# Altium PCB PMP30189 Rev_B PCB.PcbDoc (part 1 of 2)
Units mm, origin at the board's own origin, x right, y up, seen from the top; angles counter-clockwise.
Board outline 62.23 x 71.12 mm, 4 copper layers (Top Layer, Signal Layer 1, Signal Layer 2, Bottom Layer), stack 2.099 mm thick; 88 components, 42 nets, 247 pads, 90 vias.
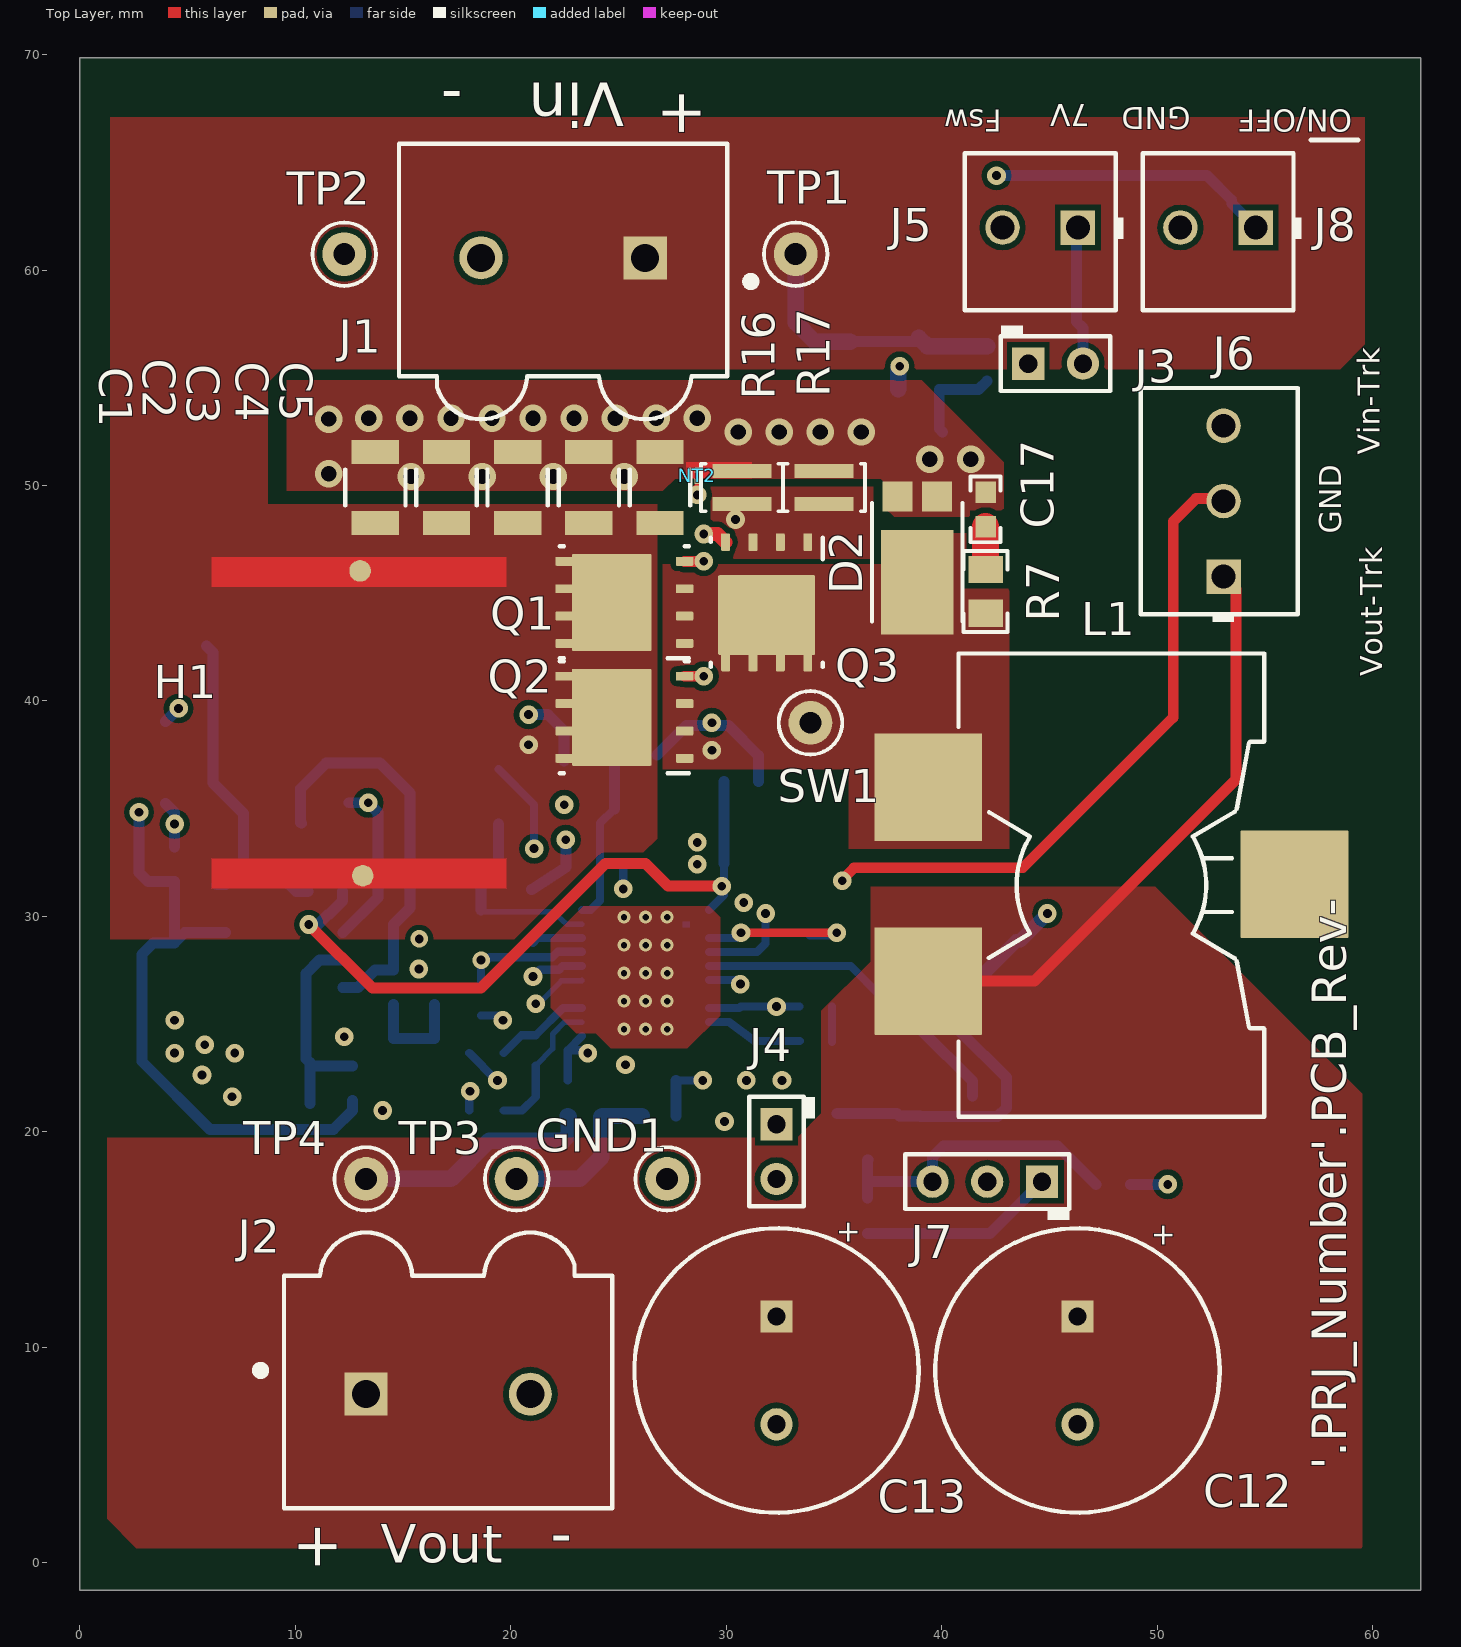
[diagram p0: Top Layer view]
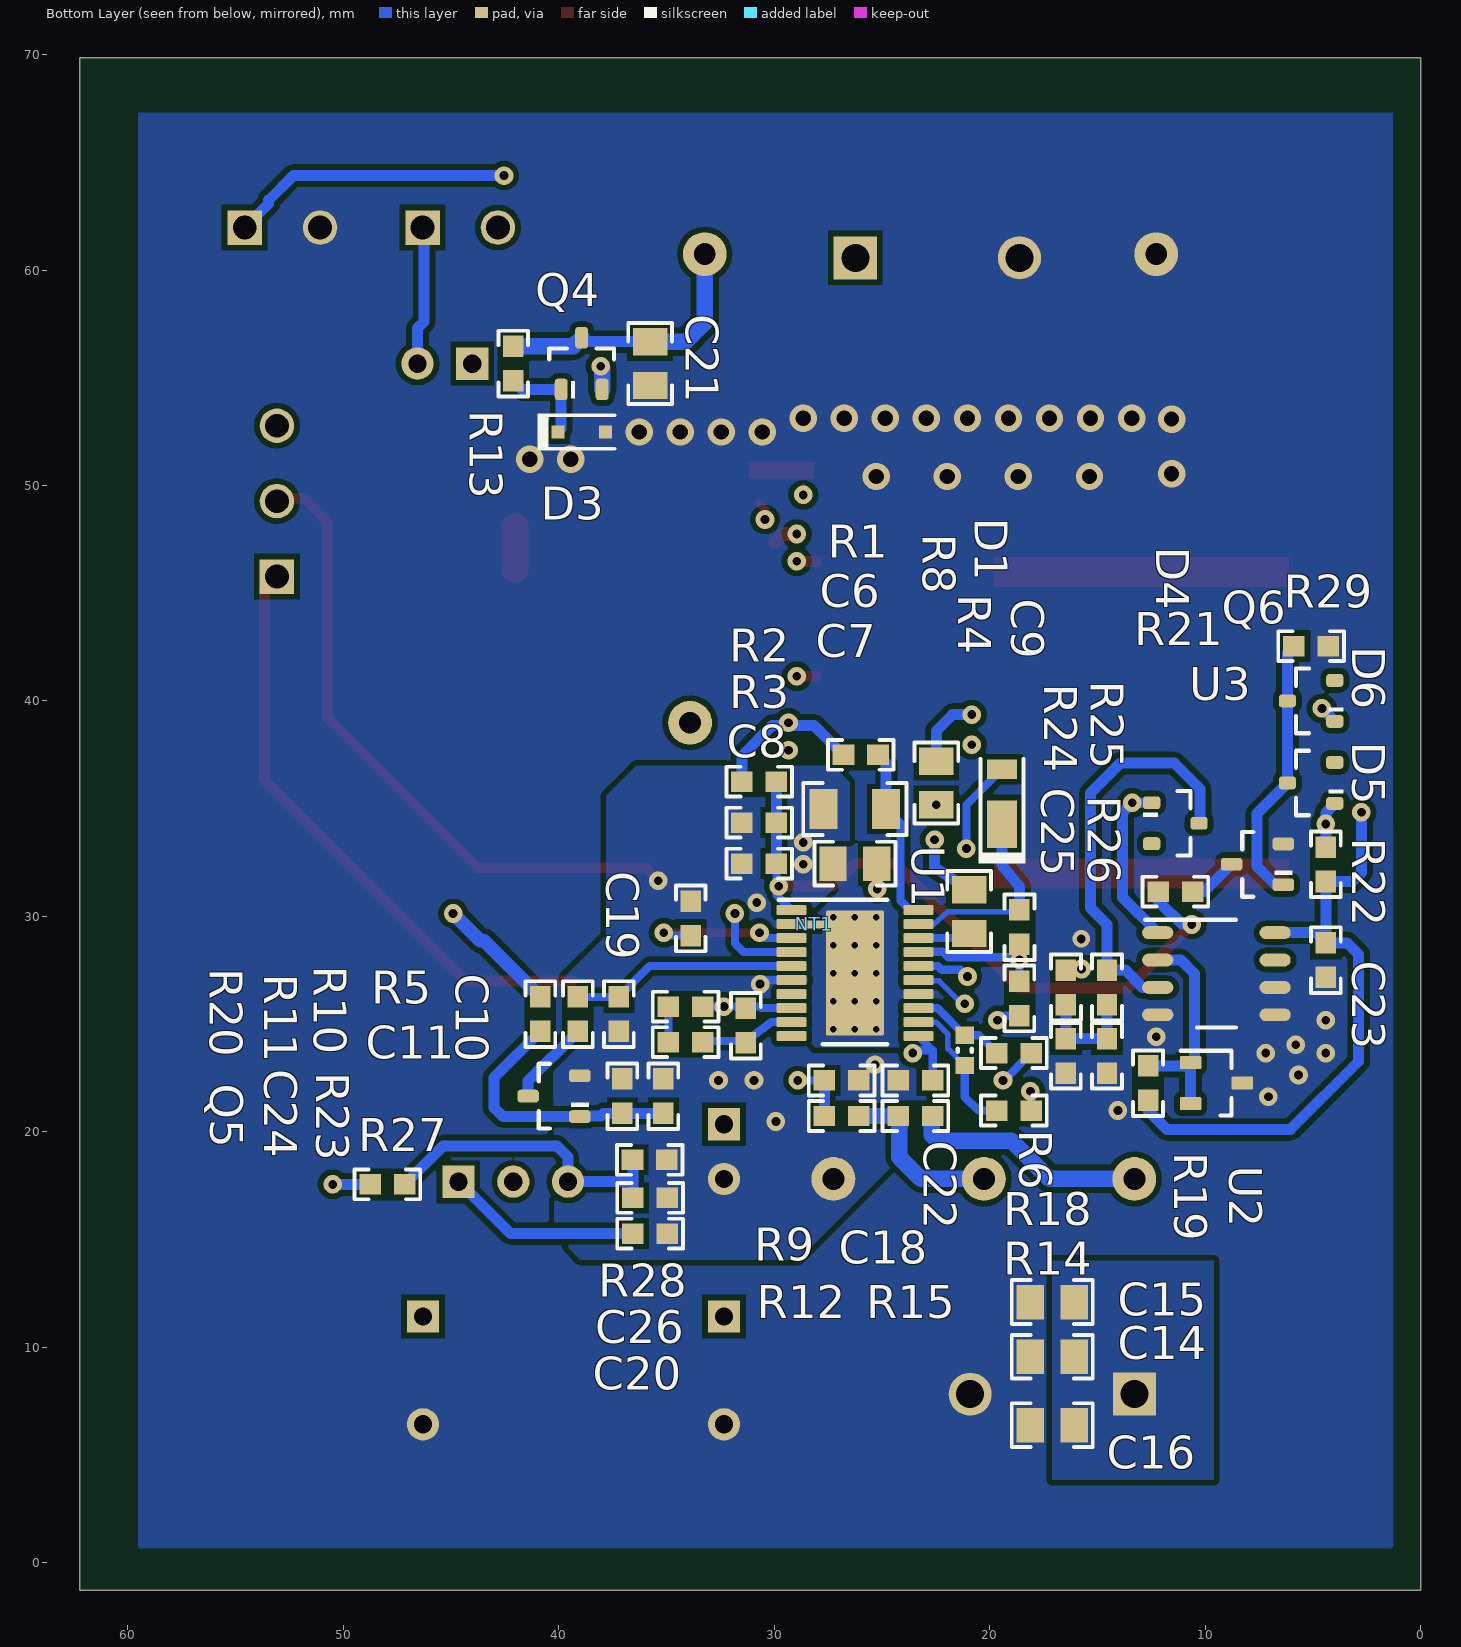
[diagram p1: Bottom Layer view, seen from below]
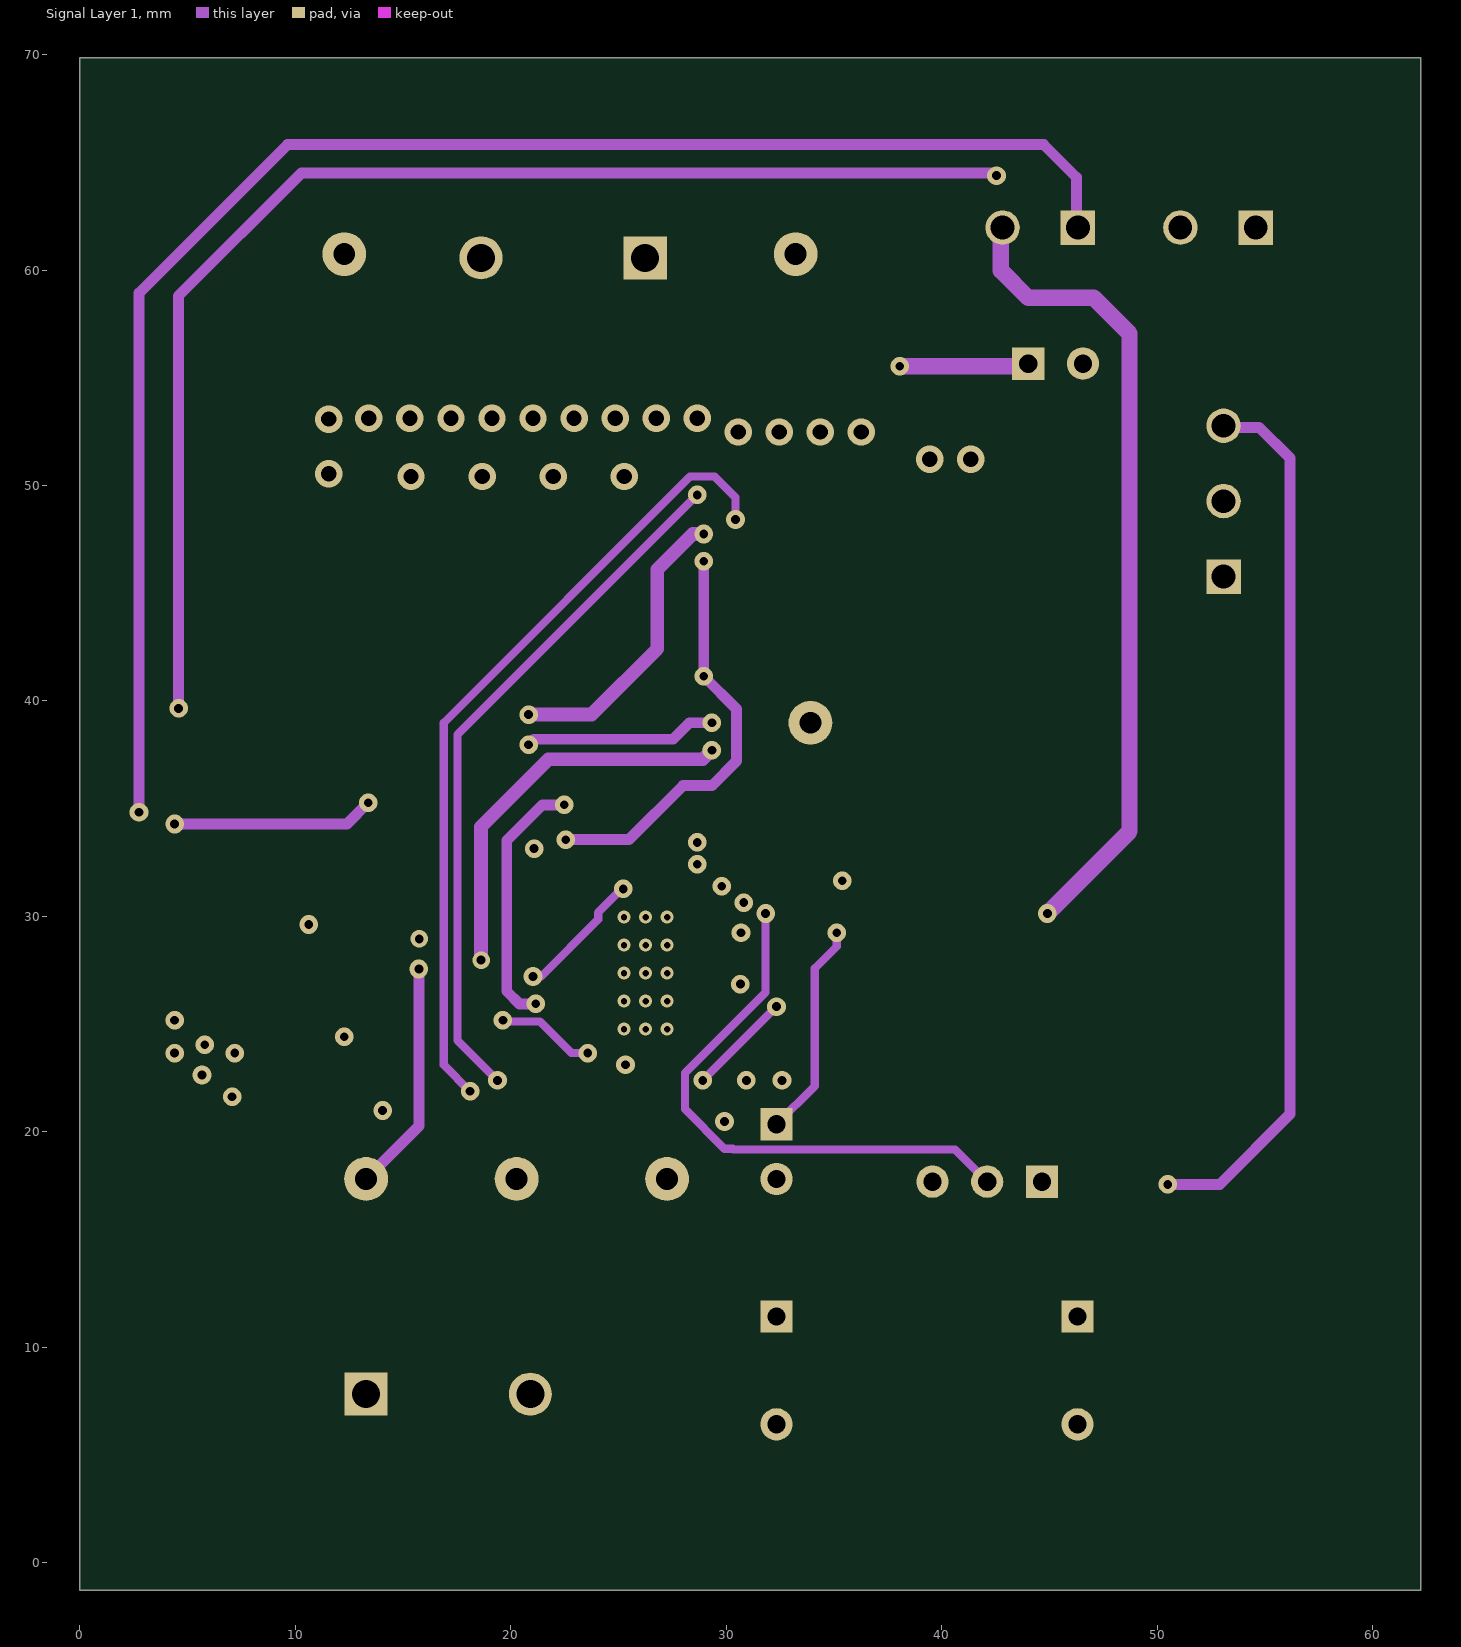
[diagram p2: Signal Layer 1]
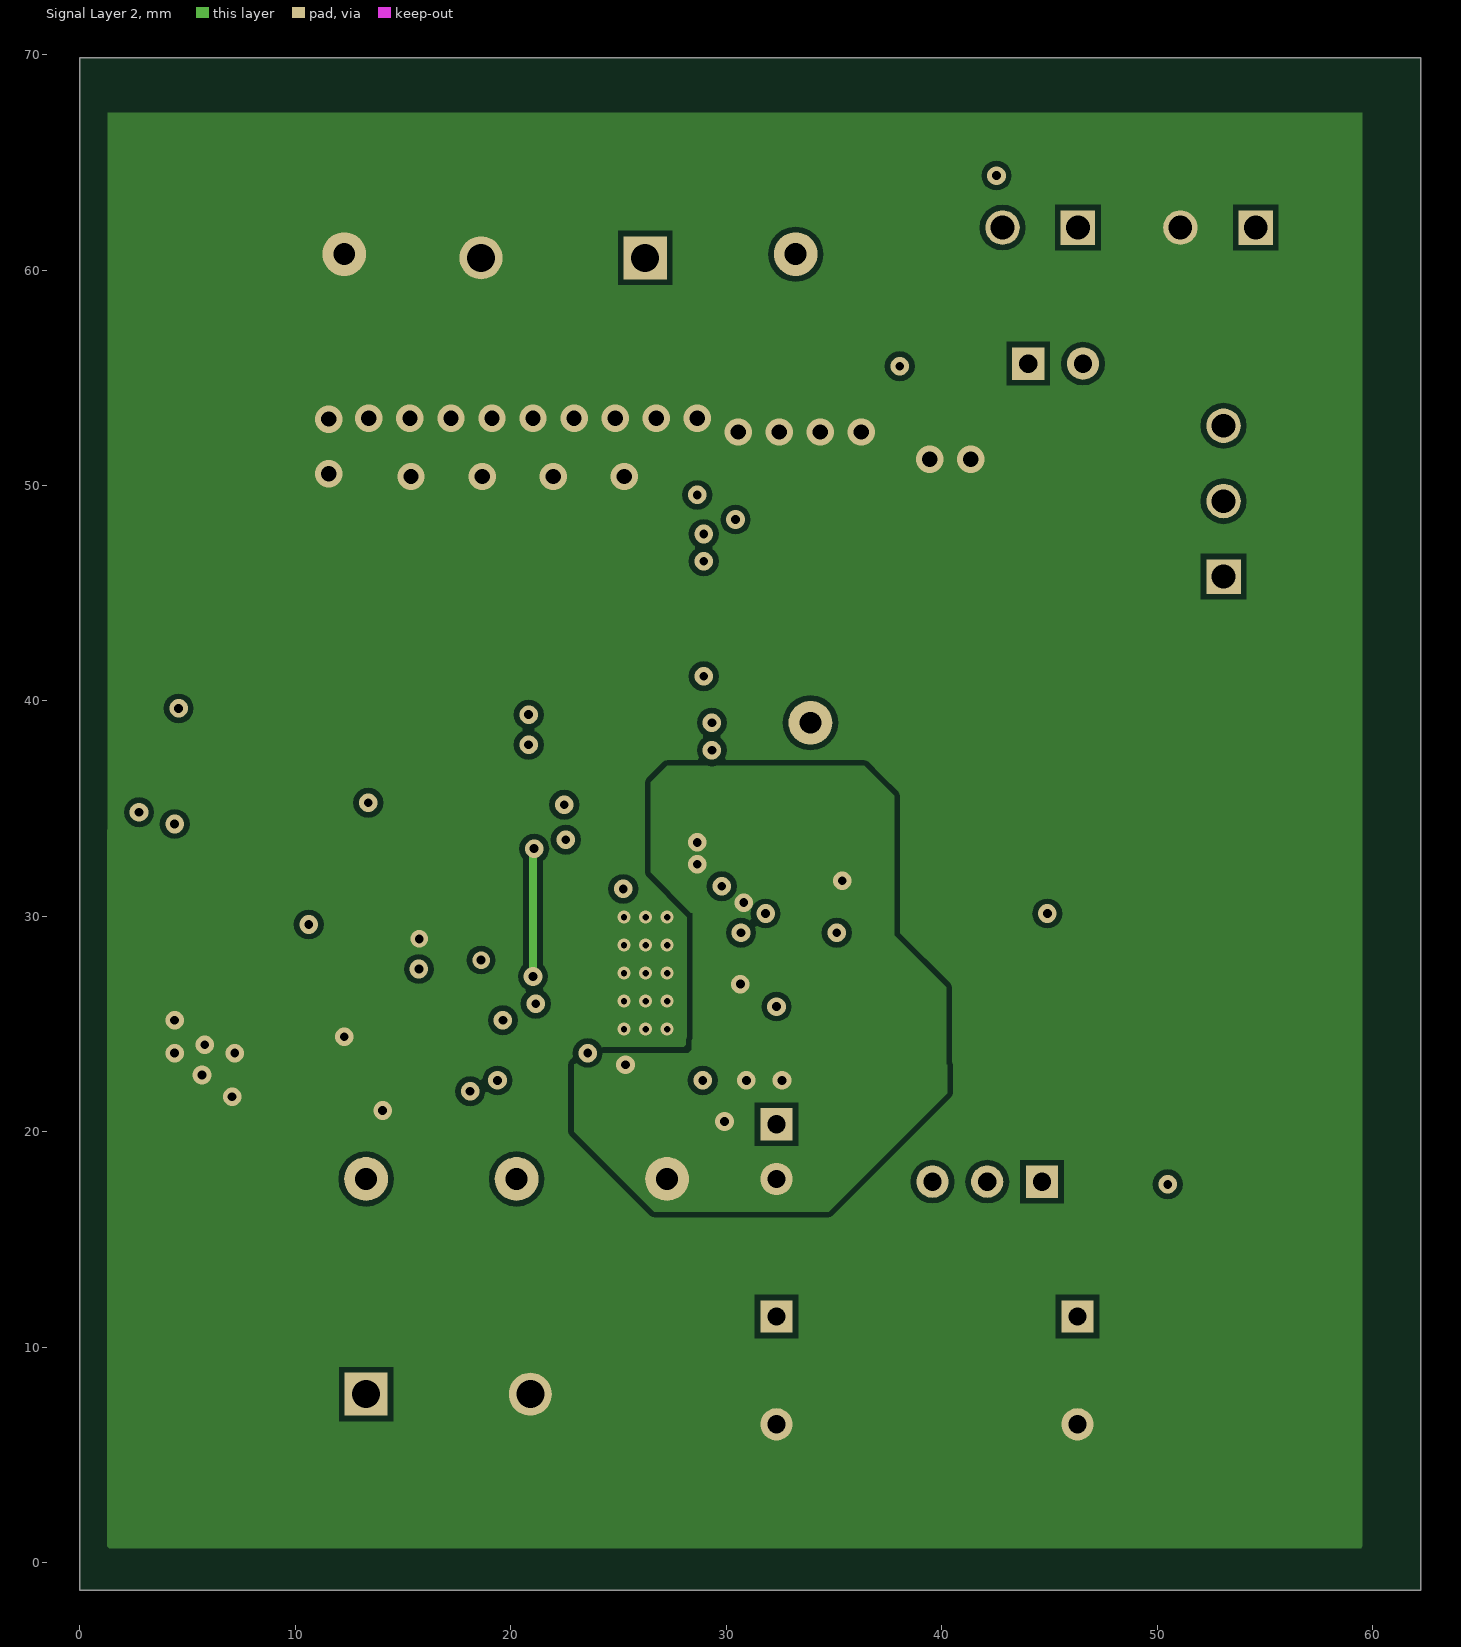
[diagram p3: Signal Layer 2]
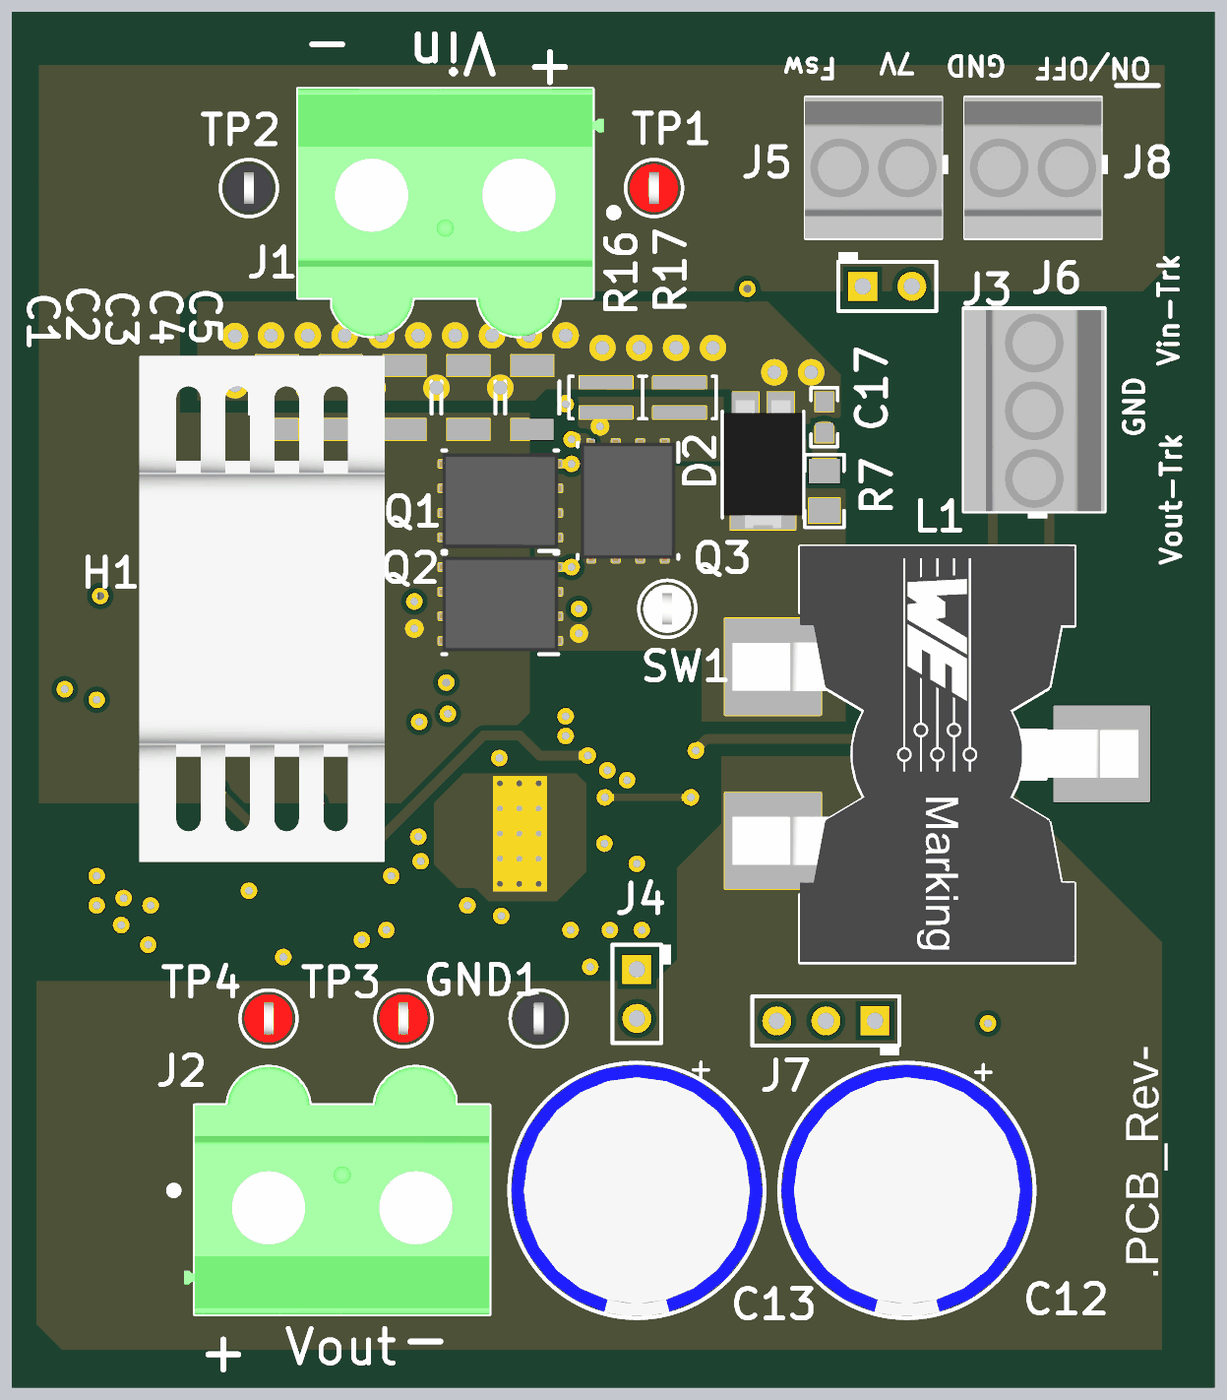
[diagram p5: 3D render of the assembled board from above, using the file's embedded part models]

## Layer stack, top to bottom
Top Solder: solder mask 0.0102, Solder Resist, Dk 3.5
Top Layer: signal copper 0.0711
Dielectric1: core 1.5037, FR-4, Dk 4.8
Signal Layer 1: signal copper 0.036
Dielectric 3: prepreg 0.127, Dk 4.2
Signal Layer 2: signal copper 0.036
Dielectric 2: core 0.254, Dk 4.2
Bottom Layer: signal copper 0.0711
Bottom Solder: solder mask 0.0102, Solder Resist, Dk 3.5

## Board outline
0,-1.27 62.23,-1.27 62.23,69.85 0,69.85

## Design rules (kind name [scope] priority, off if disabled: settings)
AcuteAngle [All] p1: minimum=4.50000000000000E+0001 checktracksonly=FALSE
AssemblyTestPointUsage [All] p1: valid=2
BoardOutlineClearance BoardOutlineClearance_MountingHoles [OnCopper and InComponentClass('Mounting Holes')] p1: gap=1.016
BoardOutlineClearance BoardOutlineClearance_Poly [OnCopper and IsPoly] p2: gap=0.635
BoardOutlineClearance [OnCopper and Not InComponentClass('Logo') and not InComponentClass('FiducialMark') and not InRegion(1000,500,4000,800) and not InPoly] p3: gap=1.905
Clearance Clearance_Keepouts [((IsTrack Or IsArc) And Not InPoly) And IsFree and IsKeepOut vs ((IsTrack Or IsArc) And Not InPoly) And IsFree and IsKeepOut] p1: gap=0
Clearance Clearance_Poly [InPolygon] p2: gap=0.254
Clearance [All] p3: gap=0.2
ComponentClearance ComponentClearance_MountingHoles_FiducialMarks [InComponentClass('Mounting Holes') vs InComponentClass('FiducialMark')] p1: gap=1.27 collisioncheckmode=3 verticalgap=0.254 showdistances=FALSE
ComponentClearance ComponentClearance_Shunt [InComponentClass('Header') vs InComponentClass('Shunt')] p2: gap=0 collisioncheckmode=3 verticalgap=0 showdistances=FALSE
ComponentClearance ComponentClearance_Logo [InComponentClass('Logo')] p3: gap=1.27 collisioncheckmode=3 verticalgap=0.254 showdistances=FALSE
ComponentClearance ComponentClearance_ScrewToNut [(HasFootprint('NY PMS 440 0025 PH')) vs (HasFootprint('Keystone_1902C'))] p4: gap=0.127 collisioncheckmode=3 verticalgap=0.254 showdistances=FALSE
ComponentClearance ComponentClearance_MountingHoles [InComponentClass('Mounting Holes')] p5: gap=6.35 collisioncheckmode=3 verticalgap=2540 showdistances=FALSE
ComponentClearance ComponentClearance_SmallPassives [HasFootprint('0201*') or HasFootprint('0402*') or HasFootprint('0508') or HasFootprint('0603*') or HasFootprint('0612') or HasFootprint('0805*') or HasFootprint('0815*') or HasFootprint('0830*') or HasFootprint('1206*') or HasFootprint('1210*') or HasFootprint('1808*') or HasFootprint('1812*') or HasFootprint('1825*') or HasFootprint('2010*') or HasFootprint('2220*') or HasFootprint('2225*') or HasFootprint('2512*') or HasFootprint('2728*') or HasFootprint('3518*') vs HasFootprint('0201*') or HasFootprint('0402*') or HasFootprint('0508') or HasFootprint('0603*') or HasFootprint('0612') or HasFootprint('0805*') or HasFootprint('0815*') or HasFootprint('0830*') or HasFootprint('1206*') or HasFootprint('1210*') or HasFootprint('1808*') or HasFootprint('1812*') or HasFootprint('1825*') or HasFootprint('2010*') or HasFootprint('2220*') or HasFootprint('2225*') or HasFootprint('2512*') or HasFootprint('2728*') or HasFootprint('3518*')] p6: gap=0.38 collisioncheckmode=3 verticalgap=0.254 showdistances=FALSE
ComponentClearance ComponentClearance_THtoSMT [IsThruComponent vs IsSMTComponent] p7: gap=0.254 collisioncheckmode=3 verticalgap=0.762 showdistances=FALSE
ComponentClearance "Net Tie 10mil" [HasFootprint('Net-Tie_10mil') vs IsSMTComponent] p8: gap=0 collisioncheckmode=3 verticalgap=0.762 showdistances=FALSE
ComponentClearance ComponentClearance_THtoTH [IsThruComponent vs IsThruComponent] p9: gap=0.254 collisioncheckmode=3 verticalgap=0.762 showdistances=FALSE
ComponentClearance [All] p10: gap=0.254 collisioncheckmode=3 verticalgap=0.254 showdistances=FALSE
DiffPairsRouting [All] p1: maxlimit=2.54 minlimit=0.254 mostfreqgap=0.254 toplayer_minwidth=0.381 toplayer_maxwidth=0.381 toplayer_prefwidth=0.381 midlayer1_minwidth=0.381 midlayer1_maxwidth=0.381 midlayer1_prefwidth=0.381 midlayer2_minwidth=0.381 midlayer2_maxwidth=0.381 midlayer2_prefwidth=0.381 bottomlayer_minwidth=0.381 bottomlayer_maxwidth=0.381 bottomlayer_prefwidth=0.381 maxuncoupledlength=25.4
FabricationTestPointUsage TestPointUsage [All] p1: valid=2 allowmultiple=FALSE
FabricationTestpoint Testpoint [All] p1: side=3 testpointundercomponent=TRUE minsize=1.016 maxsize=2.54 preferedsize=1.524 minholesize=0 maxholesize=1.016 preferedholesize=0.813 testpointgrid=0.025 allowsidetop=TRUE allowsidebottom=TRUE usegrid=TRUE gridtolerance=0
FanoutControl Fanout_LCC [IsLCC] p1: bgadir=Out bgaviamode=Centered fanoutstyle=Auto fanoutdirection=Alternating viagrid=0.025 // Fanout_LCC (Default Rule)
FanoutControl Fanout_BGA [IsBGA] p2: bgadir=Out bgaviamode=Centered fanoutstyle=Auto fanoutdirection=Alternating viagrid=0.025 // Fanout_BGA (Default Rule)
FanoutControl Fanout_Default [All] p4: bgadir=Out bgaviamode=Centered fanoutstyle=Auto fanoutdirection=Alternating viagrid=0.025 // Fanout_Default (Default Rule)
FanoutControl Fanout_Small [(CompPinCount < 5)] p5: bgadir=Out bgaviamode=Centered fanoutstyle=Auto fanoutdirection=OutThenIn viagrid=0.025 // Fanout_Small (Default Rule)
HoleSize [All] p1: absolutevalues=TRUE maxlimit=6.375 minlimit=0.3 maxpercent=80.000 minpercent=20.000
MinimumAnnularRing MinimumAnnularRing_ThermalPadVias [IsVia and InAnyComponent] p1: minimumring=0.15
MinimumAnnularRing [All] p2: minimumring=0.2
MinimumSolderMaskSliver MinimumSolderMaskSliver_Logo [InComponentClass('Logo') vs InComponentClass('Logo')] p1: minsoldermaskwidth=0.018
MinimumSolderMaskSliver [All] p2: minsoldermaskwidth=0.1
PlaneConnect [All] p1: planeconnectstyle=Relief reliefexpansion=0.254 reliefentries=4 reliefconductorwidth=0.254 reliefairgap=0.254
PolygonConnect PolygonConnect_9 [All vs IsNamedPolygon('+24V Bottom')] p1: connectstyle=Direct reliefconductorwidth=0.254 reliefentries=4 polygonreliefangle="90 Angle" airgapwidth=0.254
PolygonConnect PolygonConnect_8 [All vs IsNamedPolygon('+24V')] p2: connectstyle=Direct reliefconductorwidth=0.254 reliefentries=4 polygonreliefangle="90 Angle" airgapwidth=0.254
PolygonConnect PolygonConnect_7 [All vs IsNamedPolygon('S-GND Mid-2')] p3: connectstyle=Direct reliefconductorwidth=0.254 reliefentries=4 polygonreliefangle="90 Angle" airgapwidth=0.254
PolygonConnect PolygonConnect_6 [All vs IsNamedPolygon('S-GND Bottom')] p4: connectstyle=Direct reliefconductorwidth=0.254 reliefentries=4 polygonreliefangle="90 Angle" airgapwidth=0.254
PolygonConnect PolygonConnect_5 [All vs IsNamedPolygon('Vin')] p5: connectstyle=Direct reliefconductorwidth=0.254 reliefentries=4 polygonreliefangle="90 Angle" airgapwidth=0.254
PolygonConnect PolygonConnect_4 [All vs IsNamedPolygon('Signal Layer 1-No Net') or IsNamedPolygon('TOP_LAYER_SGND_P020')] p6: connectstyle=Direct reliefconductorwidth=0.254 reliefentries=4 polygonreliefangle="90 Angle" airgapwidth=0.254
PolygonConnect PolygonConnect_3 [All vs IsNamedPolygon('Top Layer-No Net')] p7: connectstyle=Direct reliefconductorwidth=0.254 reliefentries=4 polygonreliefangle="90 Angle" airgapwidth=0.254
PolygonConnect PolygonConnect_2 [All vs IsNamedPolygon('Switch Node')] p8: connectstyle=Direct reliefconductorwidth=0.254 reliefentries=4 polygonreliefangle="90 Angle" airgapwidth=0.254
PolygonConnect PolygonConnect_1 [All vs IsNamedPolygon('Bottom Layer-No Net')] p9: connectstyle=Direct reliefconductorwidth=0.254 reliefentries=4 polygonreliefangle="90 Angle" airgapwidth=0.254
PolygonConnect [All] p10: connectstyle=Relief reliefconductorwidth=0.254 reliefentries=4 polygonreliefangle="90 Angle" airgapwidth=0.254
RoutingVias ThermalPadVias [IsVia and InAnyComponent] p1: holewidth=0.2 width=0.5 viastyle="Through Hole" minholewidth=0.3 minwidth=0.6 maxholewidth=0.33 maxwidth=0.6
RoutingVias [All] p2: holewidth=0.406 width=0.864 viastyle="Through Hole" minholewidth=0.3 minwidth=0.66 maxholewidth=1.016 maxwidth=1.651
SilkToBoardRegionClearance [Not ((IsComment or IsDesignator) And (Hide <> 'False')) and not InRegion(1000,500,4000,800)] p1:
SilkToSilkClearance SilkToSilkClearance_Pb-FreeLogo [(HasFootprint('Pb-Free_Overlay_Medium') OR HasFootprint('Pb-Free_Overlay_Small')) vs (HasFootprint('Pb-Free_Overlay_Medium') OR HasFootprint('Pb-Free_Overlay_Small'))] p1: silktosilkclearance=0
SilkToSilkClearance [All] p2: silktosilkclearance=0.102
SilkToSolderMaskClearance SilkToComponentPadClearance [IsPad and InAnycomponent] p1: minsilkscreentomaskgap=0.127 clearancetoexposedcopper=TRUE
SilkToSolderMaskClearance "Silk to Solder Mask Opening" [All] p2: minsilkscreentomaskgap=0.102 clearancetoexposedcopper=FALSE
SolderMaskExpansion [All] p1: expansion=0.05
Width [All] p1: maxlimit=2.54 minlimit=0.152 preferedwidth=0.254 checkconnectedcopper=TRUE
15 further rules are at their usual default settings.

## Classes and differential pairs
component class Header: J3 J4 J7

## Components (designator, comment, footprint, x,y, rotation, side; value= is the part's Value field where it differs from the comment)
C1 "C3225X7R1H106M250AC" 1210_280 13.716,49.911 r90 top
C2 "C3225X7R1H106M250AC" 1210_280 17.018,49.911 r90 top
C3 "C3225X7R1H106M250AC" 1210_280 20.32,49.911 r90 top
C4 "C3225X7R1H106M250AC" 1210_280 23.622,49.911 r90 top
C5 "C3225X7R1H106M250AC" 1210_280 26.924,49.911 r90 top
C6 "GRM31MR71H105KA88L" 1206 26.255,34.99 r0 bottom
C7 "GRM21BR71C475KA73L" 0805_HV 26.255,32.45 r0 bottom
C8 "06035A101FAT2A" 0603 30.7,32.45 r0 bottom
C9 "GRM188R71E474KA12D" 0603 18.619,29.499 r270 bottom
C10 "C0603C270J5GACTU" 0603 31.319,24.927 r90 bottom
C11 "C0603C682J5RACTU" 0603 34.113,24.165 r0 bottom
C12 "50ZLH470M12.5X20" ZLH_1250x2500 46.305,8.925 r270 top
C13 "50ZLH470M12.5X20" ZLH_1250x2500 32.335,8.925 r270 top
C14 "08055C105KAT2A" 0805_HV 17.095,9.56 r0 bottom
C15 "08055C105KAT2A" 0805_HV 17.095,12.1 r0 bottom
C16 "08055C104JAT2A" 0805_HV 17.095,6.385 r0 bottom
C17 "GRM1885C1H821JA01D" 0603 42.037,48.895 r90 top
C18 "GRM1885C1H821JA01D" 0603 23.445,22.387 r0 bottom
C19 "C1608X7R1C105K080AC" 0603 33.875,29.91 r90 bottom
C20 "GRM188R71C394KA88D" 0603 35.764,15.275 r180 bottom
C21 "08055C105KAT2A" 0805_HV 35.764,55.661 r270 bottom
C22 "GRM1885C1H101JA01D" 0603L 21.159,23.784 r90 bottom
C23 "C1608X7R1C105K080AC" 0603 4.395,27.975 r270 bottom
C24 "06031C103JAT2A" 0603 37.05,21.655 r270 bottom
C25 "06031C103JAT2A" 0603 16.46,23.53 r90 bottom
C26 "06031C103JAT2A" 0603 35.762,16.938 r0 bottom
D1 "DFLS1100-7" powerDI123 19.431,35.56 r90 bottom
D2 "PDS760Q-13" PowerDI5 38.862,47.498 r270 top
D3 "MM3Z7V5B" SOD-323F 38.939,52.486 r180 bottom
D4 "BAS21-TP" SOT-23L 11.38,34.325 r180 bottom
D5 "BAS21-TP" SOT-23L 5.08,36.195 r0 bottom
D6 "BAS21-TP" SOT-23L 5.08,40.005 r0 bottom
GND1 "5001" Keystone5001 27.255,17.815 r0 top
H1 "573300D00010G" HEATSINK_573300D00010G 12.954,38.989 r90 top
J1 "1732720" Phoenix_1732720 22.429,59.471 r180 top
J2 "1732720" Phoenix_1732720 17.095,8.925 r0 top
J3 "800-10-002-10-001000" Mill-Max_800-10-002-10-001000 45.289,55.661 r0 top
J4 "800-10-002-10-001000" Mill-Max_800-10-002-10-001000 32.335,19.085 r270 top
J5 "39357-0002" Molex_39357-0002 44.577,61.976 r180 top
J6 "39357-0003" Molex_39357-0003 53.086,49.276 r90 top
J7 "800-10-003-10-001000" Mill-Max_800-10-003-10-001000 42.114,17.688 r180 top
J8 "39357-0002" Molex_39357-0002 52.832,61.976 r180 top
L1 "7443630700" WE-HCF_2013 47.879,31.496 r0 top
NT1 "Net-Tie" Net-Tie_10mil#1 28.144,29.626 r180 bottom net-tie
NT2 "Net-Tie" Net-Tie_10mil#2 28.652,50.454 r90 top net-tie
Q1 "CSD18533Q5A" DQJ0008A 25.273,44.577 r180 top
Q2 "CSD18533Q5A" DQJ0008A 25.273,39.243 r180 top
Q3 "CSD18533Q5A" DQJ0008A 31.877,44.577 r270 top
Q4 "MMBT3904LT1G" SOT-23 38.939,55.661 r90 bottom
Q5 "2N7002-7-F" SOT-23 40.225,21.655 r0 bottom
Q6 "2N7002-7-F" SOT-23 7.57,32.42 r0 bottom
R1 "CRCW06033R24FKEA" 0603 25.985,37.5 r180 bottom
R2 "CRCW0603100KFKEA" 0603 30.7,36.26 r0 bottom
R3 "RC0603FR-074K87L" 0603 30.7,34.355 r180 bottom
R4 "RC0805FR-072R21L" 0805_HV 20.955,30.226 r90 bottom
R5 "RC0603FR-07294KL" 0603 34.113,25.816 r0 bottom
R6 "RC0603FR-07187KL" 0603 18.619,26.197 r90 bottom
R7 "CRCW08051R21FKEA" 0805_HV 42.037,45.085 r270 top
R8 "RC0805FR-072R21L" 0805_HV 22.479,36.195 r90 bottom
R9 "RC0603FR-071K65L" 0603 26.874,22.387 r0 bottom
R10 "RC0603FR-07102KL" 0603 37.211,25.465 r90 bottom
R11 "RC0603FR-0724K9L" 0603 39.116,25.465 r90 bottom
R12 "RC0603FR-0747K5L" 0603 26.874,20.736 r0 bottom
R13 "RC0603FR-0747K5L" 0603 42.114,55.661 r90 bottom
R14 "RC0603FR-07100RL" 0603 18.873,20.99 r180 bottom
R15 "RC0603FR-0749R9L" 0603 23.445,20.736 r0 bottom
R16 "PRL1632-R009-F-T1" 0612 30.734,49.911 r270 top
R17 "PRL1632-R009-F-T1" 0612 34.544,49.911 r270 top
R18 "RC0603FR-07100RL" 0603 18.873,23.657 r180 bottom
R19 "RC0603FR-076K81L" 0603 12.65,22.26 r90 bottom
R20 "CRCW060310K0FKEA" 0603 40.86,25.465 r90 bottom
R21 "RC0603FR-07100RL" 0603 11.38,31.15 r0 bottom
R22 "CRCW060310K0FKEA" 0603 4.395,32.42 r90 bottom
R23 "CRCW0603100KFKEA" 0603 35.145,21.655 r270 bottom
R24 "CRCW0603100KFKEA" 0603 16.46,26.705 r270 bottom
R25 "CRCW060310K0FKEA" 0603 14.555,26.705 r90 bottom
R26 "RC0603FR-0710K5L" 0603 14.555,23.53 r90 bottom
R27 "RC0603FR-0747K5L" 0603 47.956,17.561 r180 bottom
R28 "RC0603FR-071K58L" 0603 35.781,18.704 r0 bottom
R29 "CRCW0603100KFKEA" 0603 5.08,42.545 r0 bottom
SW1 "5002" Keystone5002 33.909,38.989 r0 top
TP1 "5000" Keystone5000 33.224,60.741 r0 top
TP2 "5001" Keystone5001 12.269,60.741 r0 top
TP3 "5000" Keystone5000 20.27,17.815 r0 top
TP4 "5000" Keystone5000 13.285,17.815 r0 top
U1 "LM5117QPMH/NOPB" PWP0020A_N 26.255,27.37 r180 bottom
U2 "TL431AIDBZR" DBZ0003A_N 9.475,22.26 r180 bottom
U3 "LM2903VQDR" D0008A_N 9.475,27.34 r180 bottom

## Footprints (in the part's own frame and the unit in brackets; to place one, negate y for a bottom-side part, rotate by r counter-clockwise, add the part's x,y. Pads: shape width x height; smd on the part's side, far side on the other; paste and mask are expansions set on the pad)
0603 [mm] "0603 from SM-752 data"
  rect 1x0.95 smd: 1(-0.8,0) 2(0.8,0)
  silkscreen extent -1.52,-0.69 1.52,0.69, body extent -0.87,-0.47 0.87,0.47, height 1
0603L [mm] "0603 from SM-752 data"
  rect 0.8x0.85 smd: 1(-0.7,0) 2(0.7,0)
  silkscreen extent -0.07,-0.33 0.07,0.33, body extent -0.87,-0.47 0.87,0.47, height 1
0612 [mm] "Panasonic recommended land pattern, fb97d03ed01.pdf dated April 2008"
  rect 0.65x2.75 smd: 1(-0.775,0) 2(0.775,0)
  silkscreen extent -1.1,-1.9 1.1,1.9, body extent -0.9,-1.7 0.9,1.7, height 0.85
0805_HV [mil] "0805 with 30mil clearance between pads"
  rect 50x63 smd: 1(-40,0) 2(40,0)
  silkscreen extent -74,-40 74,40, body extent -43,-29 43,29, height 57
1206 [mm] "1206 from SM-752 data"
  rect 1.3x1.85 smd: 1(-1.45,0) 2(1.45,0)
  silkscreen extent -2.4,-1.21 2.4,1.21, body extent -1.7,-0.9 1.7,0.9, height 1.35
1210_280 [mm] "SMD, 2-Leads, Body 3.6x2.8mm, Height 2.8mm"
  rect 1.1x2.2 smd: 1(-1.65,0) 2(1.65,0)
  silkscreen extent -0.84,-1.4 0.84,1.4, body extent -1.8,-1.4 1.8,1.4, height 2.8
D0008A_N [mm] "SOIC, 8-Leads, Body 4.9x3.9mm, Pitch 1.27mm, IPC Medium Density"
  oval 1.45x0.6 smd: 1(-2.725,1.905) 2(-2.725,0.635) 3(-2.725,-0.635) 4(-2.725,-1.905) 5(2.725,-1.905) 6(2.725,-0.635) 7(2.725,0.635) 8(2.725,1.905)
  silkscreen extent -3.3,-2.5 0.9,2.5, body extent -3,-2.45 3,2.45, height 1.63
DBZ0003A_N [mm] "SOT23, 3-Leads, Body 2.9x1.3mm, Pitch 0.95mm, Lead Span 2.4mm, IPC Medium Density"
  rrect17% 1x0.6 smd: 1(-1.2,0.95) 2(-1.2,-0.95) 3(1.2,0)
  silkscreen extent -1.65,-1.5 0.7,1.5, body extent -1.26,-1.46 1.26,1.46, height 0.98
DQJ0008A [mm] "SMD, 8-Leads, Body 5.75x4.9mm"
  rrect24% 0.81x0.41 smd: 1(-2.795,1.905) 2(-2.795,0.635) 3(-2.795,-0.635) 4(-2.795,-1.905) 5(2.795,-1.905) 6(2.795,-0.635) 7(2.795,0.635) 8(2.795,1.905)
  rrect8% 1.58x1.25 on Top Paste: 9(-0.38,1.45) 9(-0.38,0) 9(-0.38,-1.45) 9(1.4,1.45) 9(1.4,0) 9(1.4,-1.45)
  rrect3% 3.7x4.5 smd paste-2.5: 9(0.59,0)
  silkscreen extent -3,-2.6 3,2.6, body extent -3.13,-2.45 3.13,2.45, height 1.15
HEATSINK_573300D00010G [mm] "Aavid"
  round 1 smd: 1(-7.1,-0.175) 2(7.05,-0.05)
  Top Layer region: -6.3,6.85 -7.7,6.85 -7.7,-6.85 -6.3,-6.85
  Top Layer region: 6.3,-6.85 7.7,-6.85 7.7,6.85 6.3,6.85
  body extent -13.08,-6.35 13.08,6.35, height 10.16
Keystone5000 [mil] "For Keystone 500x miniature loop terminals"
  round 80 hole 40: 1(0,0)
  silkscreen extent -58,-58 58,58, body extent -49,-49 49,49, height 182
Keystone5001 [mil] "For Keystone 500x miniature loop terminals"
  round 80 hole 40: 1(0,0)
  silkscreen extent -58,-58 58,58, body extent -49,-49 49,49, height 182
Keystone5002 [mil] "For Keystone 500x miniature loop terminals"
  round 80 hole 40: 1(0,0)
  silkscreen extent -58,-58 58,58, body extent -49,-49 49,49, height 182
Mill-Max_800-10-002-10-001000 [mm] "Mill-Max"
  rect 1.5x1.5 hole 0.85: 1(-1.27,0)
  round 1.5 hole 0.85: 2(1.27,0)
  silkscreen extent -2.54,-1.27 2.54,1.78, body extent -2.54,-1.27 2.54,1.27, height 8.13
Mill-Max_800-10-003-10-001000 [mm] "Mill-Max"
  rect 1.5x1.5 hole 0.85: 1(-2.54,0)
  round 1.5 hole 0.85: 2(0,0) 3(2.54,0)
  silkscreen extent -3.81,-1.27 3.81,1.78, body extent -3.81,-1.27 3.81,1.27, height 8.13
Molex_39357-0002 [mm] "Terminal Block, 3.5 mm, 2x1, TH"
  rect 1.6x1.6 hole 1.1: 1(-1.75,0)
  round 1.6 hole 1.1: 2(1.75,0)
  silkscreen extent -3.86,-3.45 3.5,3.84, body extent -3.55,-3.45 3.56,3.84, height 8.51
Molex_39357-0003 [mm] "Terminal Block, 3.5 mm, 3x1, TH"
  rect 1.6x1.6 hole 1.1: 1(-3.5,0)
  round 1.6 hole 1.1: 2(0,0) 3(3.5,0)
  silkscreen extent -5.61,-3.45 5.25,3.84, body extent -5.25,-3.45 5.16,3.84, height 8.51
Net-Tie_10mil#1 [mil] "10mil net tie, no solder mask opening, no solder paste"
  rect 30x15 smd paste-5 mask-5: 1(-10,0) 2(10,0)
  Top Layer region: -6,5 6,5 6,-5 -6,-5
Net-Tie_10mil#2 [mil] "10mil net tie, no solder mask opening, no solder paste"
  rect 10x10 smd paste-5 mask-5: 1(-10,0) 2(10,0)
  Top Layer region: -6,5 6,5 6,-5 -6,-5
Phoenix_1732720 [mm] "Phoenix Contact"
  rect 2x2 hole 1.3 paste+0 mask+0.05: 1(-3.81,-1.1)
  round 2 hole 1.3 paste+0 mask+0.05: 2(3.81,-1.1)
  silkscreen extent -8.91,-6.4 7.62,6.4, body extent -8.19,-6.4 7.62,6.4, height 18.3
PowerDI5 [mm] "Diodes Inc recommended land pattern, ap02001.pdf rev 60"
  rect 1.4x1.39 smd: 1(-1.991,0.92) 2(-1.991,-0.92)
  rect 4.86x3.36 smd: 3(1.991,0)
  silkscreen extent -1.7,-2.1 3.8,2.1, body extent -2.27,-2.03 4.33,2.03, height 1.17
powerDI123 [mm] "Diodes Inc recommended land pattern, document number DS30628 Rev. 6-2"
  rect 2.2x1.4 smd: 1(-1.275,0)
  rect 0.9x1.4 smd: 2(1.275,0)
  silkscreen extent -3.1,-1.09 1.76,1.09, body extent -2.37,-0.96 1.53,0.97, height 1
PWP0020A_N [mm] "TSOP, 20-Leads, Body 6.5x4.4mm, Pitch 0.65mm, Exposed Pad, IPC Medium Density"
  rrect22% 1.4x0.45 smd: 1(-2.95,2.925) 2(-2.95,2.275) 3(-2.95,1.625) 4(-2.95,0.975) 5(-2.95,0.325) 6(-2.95,-0.325) 7(-2.95,-0.975) 8(-2.95,-1.625) 9(-2.95,-2.275) 10(-2.95,-2.925) 11(2.95,-2.925) 12(2.95,-2.275) 13(2.95,-1.625) 14(2.95,-0.975) 15(2.95,-0.325) 16(2.95,0.325) 17(2.95,0.975) 18(2.95,1.625) 19(2.95,2.275) 20(2.95,2.925)
  rrect6% 2.7x5.8 smd paste-2 mask-2: 21(0,0)
  rrect3% 3.15x4.35 on Bottom Paste: 21(0,0)
  rrect3% 3.15x4.35 on Bottom Solder: 21(0,0)
  silkscreen extent -3.55,-3.3 1.5,3.4, body extent -3.21,-3.25 3.21,3.25, height 1
SOD-323F [mm] "NXP recommended land pattern"
  rect 0.6x0.6 smd paste-0.05: 1(-1.1,0) 2(1.1,0)
  silkscreen extent -2.06,-0.86 1.53,0.86, body extent -1.35,-0.67 1.35,0.67, height 0.79
SOT-23 [mm] "SOT23, 3-Leads, Body 2.9x1.3mm, Pitch 0.95mm, Lead Span 2.5mm, IPC Medium Density"
  rrect50% 1x0.6 smd: 1(-1.2,0.95) 2(-1.2,-0.95) 3(1.2,0)
  silkscreen extent -1.62,-1.5 0.7,1.5, body extent -1.16,-1.45 1.21,1.45, height 1
SOT-23L [mm] "SOT23, 3-Leads, Body 2.9x1.3mm, Pitch 0.95mm, Lead Span 2.5mm, IPC High Density"
  rrect50% 0.8x0.6 smd: 1(-1.1,0.95) 2(-1.1,-0.95) 3(1.1,0)
  silkscreen extent -1.5,-1.5 0.7,1.5, body extent -1.16,-1.45 1.21,1.45, height 1
WE-HCF_2013 [mm] "WURTH"
  rrect2% 5x5 smd: 1(-8.5,4.5) 2(-8.5,-4.5) 3(8.5,0)
  silkscreen extent -7.1,-10.79 7.1,10.71, body extent -10.6,-10.75 10.4,10.75, height 14.02
ZLH_1250x2500 [mm] "Rubycon"
  rect 1.5x1.5 hole 0.85: 1(-2.5,0)
  round 1.5 hole 0.85: 2(2.5,0)
  silkscreen extent -6.6,-6.6 6.6,6.6, body extent -6.45,-6.49 6.49,6.49, height 26.51

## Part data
C1 C2 C3 C4 C5: "CAP, CERM, 10 µF, 50 V, +/- 20%, X7R, 1210"
C6: "CAP, CERM, 1 µF, 50 V, +/- 10%, X7R, 1206"
C7: "CAP, CERM, 4.7 µF, 16 V, +/- 10%, X7R, 0805"
C8: "CAP, CERM, 100pF, 50V, +/-1%, C0G/NP0, 0603"
C9: "CAP, CERM, 0.47uF, 25V, +/-10%, X7R, 0603"
C10: "CAP, CERM, 27 pF, 50 V, +/- 5%, C0G/NP0, 0603"
C11: "CAP, CERM, 6800 pF, 50 V, +/- 5%, X7R, 0603"
C12 C13: library part 63ZLH470M12.5X25, "CAP, AL, 470 µF, 50 V, +/- 20%, 0.027 ohm, TH"
C14 C15 C21: "CAP, CERM, 1 µF, 50 V, +/- 10%, X7R, 0805"
C16: "CAP, CERM, 0.1uF, 50V, +/-5%, X7R, 0805"
C17: "CAP, CERM, 820pF, 50V, +/-5%, C0G/NP0, 0603"
C18: "CAP, CERM, 820 pF, 50 V, +/- 5%, C0G/NP0, 0603"
C19 C23: "CAP, CERM, 1 µF, 16 V, +/- 10%, X7R, 0603"
C20: "CAP, CERM, 0.39 µF, 16 V, +/- 10%, X7R, 0603"
C22: "CAP, CERM, 100pF, 50V, +/-5%, C0G/NP0, 0603"
C24 C25 C26: "CAP, CERM, 0.01 µF, 100 V, +/- 5%, X7R, 0603"
D1: "Diode, Schottky, 100V, 1A, PowerDI123"
D2: library part PDS560-13, "Diode, Schottky, 60 V, 7 A, PowerDI5"
D3: "Diode, Zener, 7.5 V, 200 mW, SOD-323F"
D4 D5 D6: "Diode, P-N, 200V, 200A, SOT-23"
GND1 TP2: "Test Point, Miniature, Black, TH"
H1: "Heatsink, DDPAK/TO-263, SMT"
J1 J2: "Terminal Block, 2x1, 7.62mm, TH"
J3 J4: "Header, 100mil, 2x1, TH"
J5 J8: "Terminal Block, 3.5 mm, 2x1, Tin, TH"
J6: "Terminal Block, 3.5 mm, 3x1, Tin, TH"
J7: "Header, 100mil, 3x1, TH"
L1: "Inductor, Shielded Drum Core, Mn-Zn, 7 µH, 21 A, 0.005608 ohm, SMD"
NT1 NT2: "Single point connection between nets."
Q1 Q2 Q3: "MOSFET, N-CH, 60 V, 100 A, DQJ0008A (VSONP-8)"
Q4: library part "MMBT3904LT1G, ON Semiconductor", "Transistor, NPN, 40 V, 0.2 A, SOT-23"
Q5 Q6: "MOSFET, N-CH, 60 V, 0.17 A, SOT-23"
R1: "RES, 3.24 ohm, 1%, 0.1W, 0603"
R2 R23 R24 R29: "RES, 100 k, 1%, 0.1 W, 0603"
R3: "RES, 4.87 k, 1%, 0.1 W, 0603"
R4 R8: "RES, 2.21, 1%, 0.125 W, 0805"
R5: "RES, 294 k, 1%, 0.1 W, 0603"
R6: "RES, 187 k, 1%, 0.1 W, 0603"
R7: "RES, 1.21 ohm, 1%, 0.125W, 0805"
R9: "RES, 1.65 k, 1%, 0.1 W, 0603"
R10: "RES, 102 k, 1%, 0.1 W, 0603"
R11: "RES, 24.9 k, 1%, 0.1 W, 0603"
R12 R13 R27: "RES, 47.5 k, 1%, 0.1 W, 0603"
R14 R18 R21: "RES, 100, 1%, 0.1 W, 0603"
R15: "RES, 49.9, 1%, 0.1 W, 0603"
R16 R17: "RES, 0.009, 1%, 1 W, 0612"
R19: "RES, 6.81 k, 1%, 0.1 W, 0603"
R20 R22 R25: "RES, 10.0 k, 1%, 0.1 W, 0603"
R26: "RES, 10.5 k, 1%, 0.1 W, 0603"
R28: "RES, 1.58 k, 1%, 0.1 W, 0603"
SW1: "Test Point, Miniature, White, TH"
TP1 TP3 TP4: "Test Point, Miniature, Red, TH"
U1: library part LM25117QPMH/NOPB, "Wide Input Range Synchronous Buck Controller with Analog Current Monitor, PWP0020A (TSSOP-20)"
U2: "Adjustable Precision Shunt Regulator, 34 ppm / degC, 100 mA, -40 to 85 degC, 3-pin SOT-23 (DBZ), Green (RoHS & no Sb/Br)"
U3: library part LM2903AVQD, "Dual Comparator, D0008A"

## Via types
v1: diameter 0.864, hole 0.406, Top Layer to Bottom Layer, 51 vias
v2: diameter 1.27, hole 0.711, Top Layer to Bottom Layer, 21 vias
v3: diameter 0.6, hole 0.3, Top Layer to Bottom Layer, 9 vias
v4: diameter 0.6, hole 0.3, Top Layer to Bottom Layer, tented both sides, 6 vias
v5: diameter 0.813, hole 0.406, Top Layer to Bottom Layer, 2 vias
v6: diameter 0.864, hole 0.406, Top Layer to Bottom Layer, tented bottom, 1 vias

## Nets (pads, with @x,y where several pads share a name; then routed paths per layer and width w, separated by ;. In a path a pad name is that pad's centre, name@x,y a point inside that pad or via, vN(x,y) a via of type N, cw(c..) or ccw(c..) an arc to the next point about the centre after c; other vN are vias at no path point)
24V: C12.1 C13.1 C14.1 C15.1 C16.1 J2.1 J6.1 L1.2 R15.1 R24.1 TP4.1 | length 49.7
  Top Layer w0.508: L1.2@39.379,26.996 44.31,26.996 53.671,36.357 53.671,45.191 J6.1@53.086,45.776
  Signal Layer 1 w0.508: TP4.1@13.285,17.815 15.735,20.265 v1(15.735,27.559)
  Bottom Layer w0.762: TP4.1@13.285,17.815 17.222,17.815 19,19.593 22.429,19.593 22.683,19.847 22.683,20.698 R15.1@22.645,20.736
FSW_CHANGE: J5.2 R20.2 | length 43.4
  Signal Layer 1 w0.762: J5.2@42.749,62.011 42.749,59.979 44.019,58.709 47.067,58.709 48.718,57.058 48.718,33.944 v1(44.908,30.134)
  Bottom Layer w0.635: R20.2@40.86,26.265 43.459,28.864 43.638,28.864 v1(44.908,30.134)
GND-1: C6.2 C8.2 C18.2 C19.2 C20.2 C24.1 C26.1 GND1.1 J4.2 J6.2 NT1.1 Q5.2 R3.1 R9.1 R10.1 R23.1 R28.1 U1.2 U1.6 | length 32
  Top Layer w0.508: v1(35.383,31.658) 35.383,31.7 35.941,32.258 43.765,32.258 50.75,39.243 50.75,48.337 51.816,49.403 52.959,49.403 J6.2@53.086,49.276
  Bottom Layer w0.381: U1.6@29.205,27.045 30.471,27.045 v1(30.659,26.858)
  other v1: 29.922,20.482 30.938,22.387 32.589,22.387 25.324,23.112 30.811,30.642 28.652,32.42 28.652,33.436
NetC6_1: C6.1 R1.2 U1.20 | length 8.2
  Bottom Layer w0.381: U1.20@23.305,30.295 23.71,30.295 24.145,30.731 24.145,34.33 C6.1@24.805,34.99
  Bottom Layer w0.508: C6.1@24.805,34.99 24.805,37.12 R1.2@25.185,37.5
NetC9_1: C9.1 D1.1 U1.19 | length 9.2
  Bottom Layer w0.254: C9.1@18.619,30.299 18.693,30.226 21.931,30.226 22.606,29.626 23.286,29.626 U1.19@23.305,29.645
  Bottom Layer w0.508: C9.1@18.619,30.299 18.619,31.399 19.431,32.385 D1.1@19.431,34.285
NetC9_2: C9.2 D2.3 L1.1 Q1.1 Q1.2 Q1.3 Q2.1 Q2.2 Q2.3 Q3.5 Q3.6 Q3.7 Q3.8 Q3.9@31.877,43.987 R6.2 R7.2 SW1.1 U1.17 | length 24.2
  Signal Layer 1 w0.635: v5(18.619,27.976) 18.619,34.16 21.754,37.295 28.913,37.295 v1(29.337,37.719)
  Bottom Layer w0.381: R6.2@18.619,26.998 v5(18.619,27.976) ; v5@18.669,27.747 19.024,28.102 21.921,28.102 22.175,28.356 23.294,28.356 U1.17@23.305,28.345
NetC10_1: C10.1 C11.1 U1.9 | length 4.5
  Bottom Layer w0.381: U1.9@29.205,25.095 30.135,25.095 31.319,24.215 C11.1@33.416,24.215
NetC10_2: C10.2 R5.1 R9.2 R12.2 U1.8 | length 11.9
  Signal Layer 1 w0.381: v1(28.906,22.387) v1(32.335,25.816)
  Bottom Layer w0.381: R9.2@27.674,22.387 v1(28.906,22.387) ; U1.8@29.205,25.745 30.607,25.745 30.678,25.816 v1(32.335,25.816) ; v1@32.355,25.816 R5.1@33.401,25.816
  Bottom Layer w0.508: R12.2@27.674,20.736 R9.2@27.674,22.387
NetC11_2: C11.2 R5.2 | length 1.7
  Bottom Layer w0.381: C11.2@34.913,24.165 R5.2@34.913,25.816
NetC17_1: C17.1 R7.1 | length 2
  Top Layer w1.27: R7.1@42.037,46.101 C17.1@42.037,48.095
NetC18_1: C18.1 R6.1 U1.11 | length 9
  Signal Layer 1 w0.381: v1(19.635,25.181) 19.696,25.121 21.347,25.121 22.81,23.657 v1(23.572,23.657)
  Bottom Layer w0.381: R6.1@18.619,25.397 19.419,25.397 v1(19.635,25.181) ; C18.1@22.645,22.387 22.645,23.785 ; U1.11@23.305,24.445 22.645,23.785 ; v1(23.572,23.657) 23.444,23.785 22.645,23.785
NetC19_1: C19.1 J4.1 U1.3 | length 17.4
  Top Layer w0.381: v1(30.684,29.245) v1(35.129,29.245)
  Signal Layer 1 w0.381: J4.1@32.335,20.355 34.113,22.133 34.113,27.594 35.129,28.61 v1(35.129,29.245)
  Bottom Layer w0.381: U1.3@29.205,28.995 30.434,28.995 v1(30.684,29.245) ; C19.1@33.875,29.11 34.994,29.11 v1(35.129,29.245)
NetC20_1: C20.1 J7.1 | length 9.1
  Bottom Layer w0.508: C20.1@36.564,15.275 42.241,15.275 J7.1@44.654,17.688
NetC22_1: C22.1 R14.1 U1.12 | length 6.6
  Bottom Layer w0.254: C22.1@21.159,23.084 21.937,23.862 21.937,24.53 22.502,25.095 U1.12@23.305,25.095
  Bottom Layer w0.381: R14.1@19.673,20.99 20.524,20.99 21.159,21.625 C22.1@21.159,23.084
NetC22_2: C22.2 R18.1 U1.13 | length 4.5
  Bottom Layer w0.381: R18.1@19.673,23.657 20.5,24.484 C22.2@21.159,24.484 22.42,25.745 U1.13@23.305,25.745
NetC23_1: C23.1 J3.2 J5.1 R19.1 R22.1 U3.8 | length 108.5
  Signal Layer 1 w0.508: v1(2.744,34.833) 2.744,58.928 9.638,65.821 44.739,65.821 46.249,64.311 J5.1@46.249,62.011
  Bottom Layer w0.508: v1(2.744,34.833) 2.744,32.039 3.163,31.62 R22.1@4.395,31.62 C23.1@4.395,28.775 ; U3.8@6.75,29.245 4.865,29.245 C23.1@4.395,28.775 ; R19.1@12.65,21.46 12.65,20.99 11.761,20.101 6.046,20.101 2.871,23.276 2.871,28.229 3.417,28.775 C23.1@4.395,28.775 ; J5.1@46.249,62.011 46.249,57.622 46.559,57.312 J3.2@46.559,55.661
NetC24_2: C24.2 Q5.1 R20.1 R23.2 | length 12.5
  Bottom Layer w0.508: R23.2@35.145,20.855 C24.2@37.05,20.855 37.931,20.855 38.05,20.736 38.994,20.736 Q5.1@39.025,20.705 42.591,20.705 43.003,21.117 43.003,22.522 R20.1@40.86,24.665 R20.1@40.844,24.649
NetC25_2: C25.2 R24.2 R25.1 R26.2 | length 5.1
  Bottom Layer w0.508: R25.1@14.555,25.905 R26.2@14.555,24.33 C25.2@16.46,24.33 R24.2@16.46,25.905
NetC26_2: C26.2 J7.3 R27.2 R28.2 | length 14.5
  Bottom Layer w0.508: C26.2@36.562,16.938 36.562,17.688 ; R28.2@36.581,18.704 36.562,18.685 36.562,17.688 ; R27.2@47.156,17.561 45.378,19.339 40.082,19.339 39.574,18.831 J7.3@39.574,17.688 36.562,17.688
NetD3_1: D3.1 Q4.1 R13.1 | length 4.4
  Bottom Layer w0.508: D3.1@40.039,52.486 39.889,52.636 Q4.1@39.889,54.461 41.714,54.461 R13.1@42.114,54.861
